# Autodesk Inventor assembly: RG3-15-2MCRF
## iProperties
Created: 2008-09
Part Number: RG3-15-2MCRF
Document SubType Name: Assembly
Designer: TMT
Description: Rollringgetriebe Baureihe RG Welle Rd. 15
Vendor: Uhing
Author: TMT
Comments: Uhing
